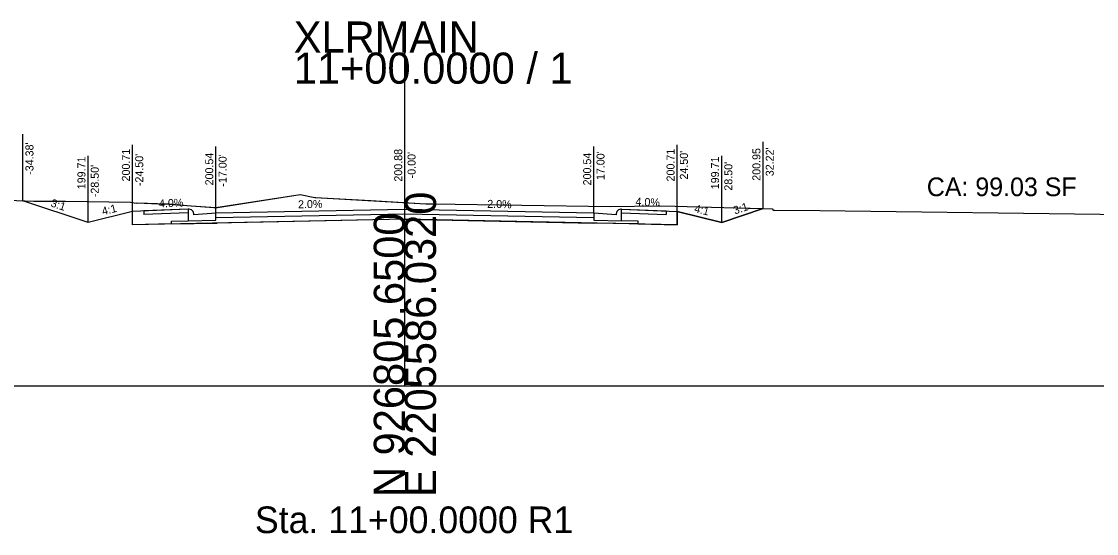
# Model space of a CAD drawing. Extents: x -26 to 303, y -13 to 1528.
# Drawn here: x 115.5 to 212.2, y 486.7 to 532.8 of the extents above; entities that cross this region are included whole.
import ezdxf

# ---------------------------------------------------------------- set-up
doc = ezdxf.new("R2010")
doc.units = 0
for name, color, linetype in [('CONST_DCH', 7, 'Continuous'), ('CONST_LV3', 7, 'Continuous'), ('Draft_XS_Text', 7, 'Continuous'), ('DTM_TEMP_DROP', 7, 'Continuous'), ('DTM_X_BOUNDARY', 7, 'Continuous'), ('SLOPE_STAKES_FILL', 7, 'Continuous'), ('XS_CELL', 7, 'Continuous'), ('XS_M_SHAPES_EARTHWORK', 7, 'Continuous'), ('XS_P_ASPHALT', 7, 'Continuous'), ('XS_P_CONCRETE', 7, 'Continuous'), ('XS_P_GROUND', 7, 'Continuous'), ('XS_P_SHOULDER', 7, 'Continuous'), ('XS_P_SUBGRADE_GRANULAR', 7, 'Continuous'), ('XS_P_SUBGRADE_GRANULAR_B', 7, 'Continuous'), ('XS_P_TX_CLEARZONE', 7, 'Continuous'), ('XS_P_TX_FS_BS', 7, 'Continuous'), ('XS_SHEET_EW_TX_AREA', 7, 'Continuous')]:
    doc.layers.add(name, color=color, linetype=linetype)

msp = doc.modelspace()

# ---------------------------------------------------------------- linework, layer by layer
at = {"layer": 'CONST_LV3'}
for points in [[(129, 514.58), (129, 514.833), (130.5, 514.863)], [(171, 514.58), (171, 514.833), (169.5, 514.863)]]:
    msp.add_lwpolyline(points, dxfattribs=at)
at = {"layer": 'DTM_X_BOUNDARY'}
msp.add_lwpolyline([(109.537, 516.912), (116.609, 516.632), (119.476, 516.618), (125.304, 516.529), (125.825, 516.46), (125.9, 516.488), (127.818, 516.387), (128.668, 516.374), (128.761, 516.372), (132.796, 516.051), (132.806, 516.051), (133.153, 516.045), (140.58, 517.218), (141.883, 516.965), (142.001, 516.963), (151.87, 516.399), (152.512, 516.389), (168.519, 516.143), (172.765, 516.213), (172.929, 516.211), (174.31, 516.19), (183.053, 515.929), (183.128, 515.814), (183.245, 515.821), (187.32, 515.793), (269.82, 514.701)], dxfattribs=at)
at = {"layer": 'XS_CELL'}
for p, q in [((150, 500), (150, 530)), ((0, 500), (150, 500)), ((150, 500), (300, 500))]:
    msp.add_line(p, q, dxfattribs=at)
at = {"layer": 'XS_M_SHAPES_EARTHWORK'}
msp.add_lwpolyline([(150, 515), (125.501, 514.509), (125.5, 515.713), (121.5, 514.713), (115.624, 516.671), (119.476, 516.618), (125.304, 516.529), (125.825, 516.46), (125.9, 516.488), (128.668, 516.374), (130.778, 516.212), (132.98, 516.048), (140.58, 517.218), (141.883, 516.965), (146.935, 516.681), (151.87, 516.399), (152.512, 516.389), (160.515, 516.266), (168.519, 516.143), (172.765, 516.213), (174.31, 516.19), (178.682, 516.059), (182.223, 515.954), (178.5, 514.713), (174.5, 515.713), (174.499, 514.509)], close=True, dxfattribs=at)
at = {"layer": 'XS_P_ASPHALT'}
for p, q in [((150, 515.878), (133, 515.538)), ((133, 515.538), (133, 515.538)), ((167, 515.538), (150, 515.878)), ((150, 515.878), (150, 515.878)), ((150, 515.878), (150, 515.878)), ((167, 515.538), (167, 515.538)), ((150.008, 515.461), (133.008, 515.121)), ((166.992, 515.121), (149.992, 515.461)), ((150, 515.128), (150, 515.128)), ((150, 515.128), (150, 515.128))]:
    msp.add_line(p, q, dxfattribs=at)
at = {"layer": 'XS_P_CONCRETE'}
for p, q in [((126.5, 515.753), (126.5, 515.422)), ((130.513, 515.583), (126.5, 515.422)), ((169.487, 515.583), (173.5, 515.422)), ((173.5, 515.753), (173.5, 515.422))]:
    msp.add_line(p, q, dxfattribs=at)
for points in [[(130.5, 515.913), (126.5, 515.753)], [(133, 515.538), (131, 515.413), (131, 515.496), (131, 515.496), (130.944, 515.704), (130.944, 515.704), (130.792, 515.857), (130.792, 515.857), (130.583, 515.913), (130.583, 515.913), (130.5, 515.913), (130.5, 515.913), (130.5, 515.913), (130.5, 514.863), (133, 514.913), (133, 514.913), (133, 515.538), (133, 515.538), (133, 515.538)], [(167, 515.538), (167, 515.538), (167, 515.538), (167, 514.913), (167, 514.913), (169.5, 514.863), (169.5, 515.913), (169.5, 515.913), (169.417, 515.913), (169.417, 515.913), (169.417, 515.913), (169.208, 515.857), (169.208, 515.857), (169.056, 515.704), (169.056, 515.704), (169, 515.496), (169, 515.496), (169, 515.413), (167, 515.538)], [(169.5, 515.913), (173.5, 515.753)]]:
    msp.add_lwpolyline(points, dxfattribs=at)
at = {"layer": 'XS_P_GROUND'}
for points in [[(121.5, 514.713), (115.624, 516.671)], [(125.5, 515.713), (121.5, 514.713)], [(174.5, 515.713), (178.5, 514.713)], [(178.5, 514.713), (182.223, 515.954)]]:
    msp.add_lwpolyline(points, dxfattribs=at)
at = {"layer": 'XS_P_SHOULDER'}
for points in [[(130.5, 515.913), (125.5, 515.713)], [(169.5, 515.913), (174.5, 515.713)]]:
    msp.add_lwpolyline(points, dxfattribs=at)
at = {"layer": 'XS_P_SUBGRADE_GRANULAR'}
for points in [[(129, 514.58), (133.119, 514.662)], [(150, 515), (133, 514.66)], [(150, 515), (167, 514.66)], [(171, 514.58), (167, 514.66)]]:
    msp.add_lwpolyline(points, dxfattribs=at)
at = {"layer": 'XS_P_SUBGRADE_GRANULAR_B'}
for points in [[(125.501, 514.509), (125.5, 515.713)], [(174.499, 514.509), (174.5, 515.713)], [(129, 514.58), (125.501, 514.509)], [(171, 514.58), (174.499, 514.509)]]:
    msp.add_lwpolyline(points, dxfattribs=at)
at = {"layer": 'XS_P_TX_CLEARZONE'}
for p, q in [((115.624, 516.671), (115.624, 522.671)), ((125.5, 515.713), (125.5, 521.713)), ((125.5, 515.713), (125.5, 521.713)), ((133, 515.538), (133, 521.538)), ((150, 515.878), (150, 521.878)), ((167, 515.538), (167, 521.538)), ((174.5, 515.713), (174.5, 521.713)), ((174.5, 515.713), (174.5, 521.713)), ((182.223, 515.954), (182.223, 521.954)), ((182.223, 515.954), (182.223, 521.954)), ((121.5, 514.713), (121.5, 520.713)), ((178.5, 514.713), (178.5, 520.713))]:
    msp.add_line(p, q, dxfattribs=at)

# ---------------------------------------------------------------- texts
at = {"layer": 'CONST_DCH'}
for p in [(132.996, 515.532), (149.996, 515.872), (166.996, 515.532)]:
    msp.add_text('X', height=0.012, dxfattribs=at).set_placement(p)
at = {"layer": 'Draft_XS_Text'}
msp.add_text('Sta. 11+00.0000 R1', height=2.4, dxfattribs=at).set_placement((136.508, 486.75))
at = {"layer": 'DTM_TEMP_DROP'}
for p in [(121.496, 514.707), (178.496, 514.707)]:
    msp.add_text('X', height=0.012, dxfattribs=at).set_placement(p)
at = {"layer": 'SLOPE_STAKES_FILL'}
for p in [(125.496, 515.707), (174.496, 515.707)]:
    msp.add_text('X', height=0.012, dxfattribs=at).set_placement(p)
at = {"layer": 'XS_CELL'}
for s, p in [('XLRMAIN', (140, 530)), ('11+00.0000 / 1', (140, 527.2))]:
    msp.add_text(s, height=2.8, dxfattribs=at).set_placement(p)
for s, p in [('E 2205586.0320', (152.8, 490)), ('N 926805.6500', (150, 490))]:
    msp.add_text(s, height=2.8, rotation=90, dxfattribs=at).set_placement(p)
at = {"layer": 'XS_P_CONCRETE'}
for p in [(115.62, 516.665), (182.22, 515.948)]:
    msp.add_text('X', height=0.012, dxfattribs=at).set_placement(p)
at = {"layer": 'XS_P_TX_CLEARZONE'}
for s, p in [("-34.38'", (116.584, 518.999)), ('200.71', (125.26, 518.403)), ('200.71', (125.26, 518.403)), ('200.88', (149.76, 518.387)), ('200.71', (174.26, 518.403)), ('200.71', (174.26, 518.403)), ('200.95', (181.983, 518.463)), ('200.95', (181.983, 518.463)), ("32.22'", (183.183, 518.871)), ("32.22'", (183.183, 518.871)), ('199.71', (121.26, 517.698)), ("-24.50'", (126.46, 517.984)), ("-24.50'", (126.46, 517.984)), ('200.54', (132.76, 518.047)), ("-17.00'", (133.96, 517.934)), ("-0.00'", (150.96, 518.682)), ('200.54', (166.76, 518.047)), ("17.00'", (167.96, 518.523)), ("24.50'", (175.46, 518.573)), ("24.50'", (175.46, 518.573)), ('199.71', (178.26, 517.698)), ("-28.50'", (122.46, 516.984)), ("28.50'", (179.46, 517.573))]:
    msp.add_text(s, height=0.72, rotation=90, dxfattribs=at).set_placement(p)
at = {"layer": 'XS_P_TX_FS_BS'}
for s, rotation, p in [('3:1', 341.56505, (118.076, 516.17)), ('4.0%', 2.33743, (127.891, 516.056)), ('2.0%', 1.14576, (140.392, 515.985)), ('2.0%', 358.85424, (157.404, 516.029)), ('4.0%', 357.63463, (170.732, 516.233)), ('3:1', 18.43495, (179.686, 515.424)), ('4:1', 14.03624, (122.833, 515.355)), ('4:1', 345.96376, (175.979, 515.652))]:
    msp.add_text(s, height=0.72, rotation=rotation, dxfattribs=at).set_placement(p)
at = {"layer": 'XS_SHEET_EW_TX_AREA'}
msp.add_text('CA: 99.03 SF', height=1.68, dxfattribs=at).set_placement((196.951, 517.079))

doc.saveas('drawing.dxf')
